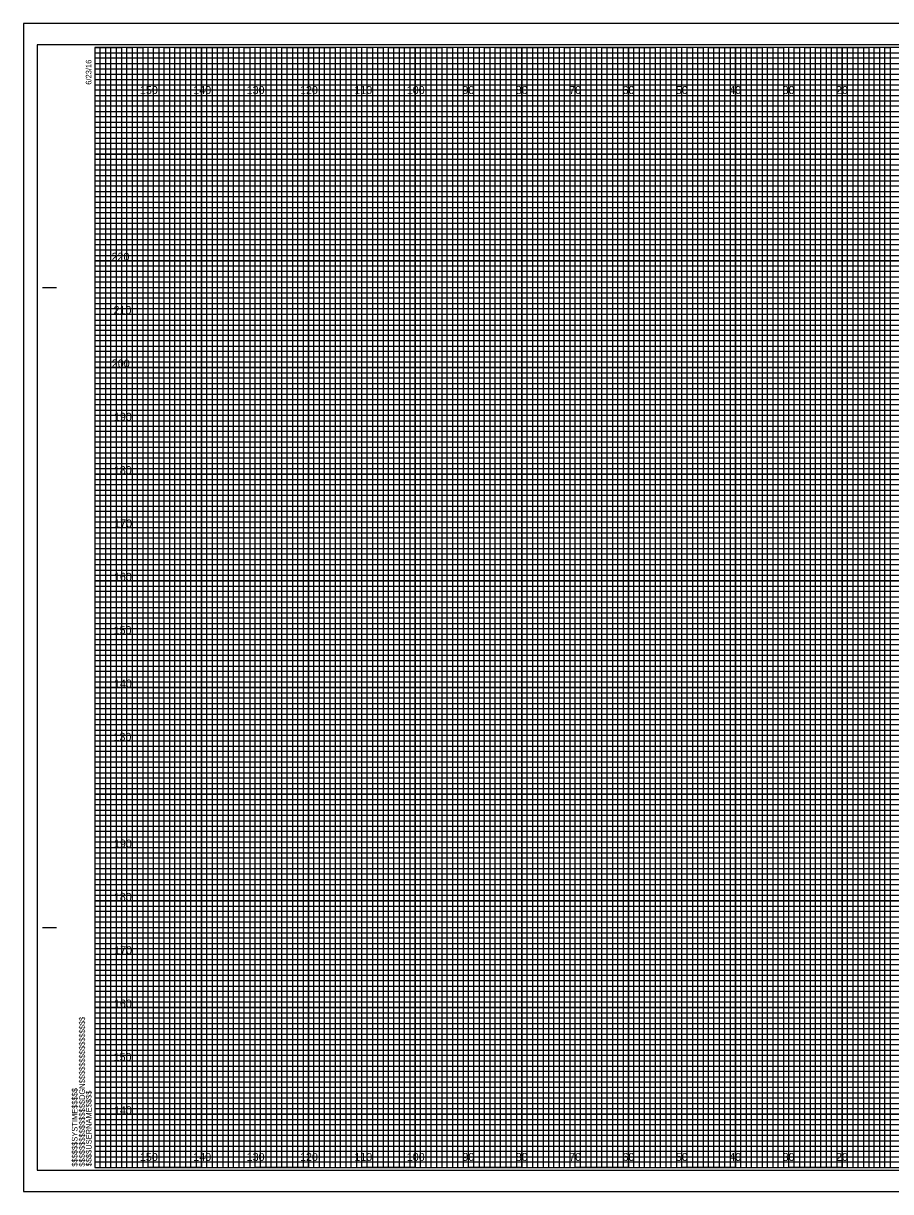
# Model space of a CAD drawing. Extents: x -13 to 323, y -5 to 1754.
# Drawn here: x -13.4 to 149.1, y 655.5 to 874.5 of the extents above; entities that cross this region are included whole.
import ezdxf

# ---------------------------------------------------------------- set-up
doc = ezdxf.new("R2010")
doc.units = 0
for name, color, linetype in [('Exist Cross Section Cell', 7, 'Continuous'), ('Exist XS Center Line Elevation Label', 7, 'Continuous'), ('Exist XS Ground Line', 7, 'Continuous'), ('Prop CMT Pvmt Course 1', 7, 'Continuous'), ('Prop CMT Pvmt Course 2', 7, 'Continuous'), ('Prop CMT Pvmt Course 3', 7, 'Continuous'), ('Prop CMT Shld Paved Course 1', 7, 'Continuous'), ('Prop CMT Shld Paved Course 2', 7, 'Continuous'), ('Prop CMT Subgrade Earthwork', 7, 'Continuous'), ('Prop XS Ditch Standard Text', 7, 'Continuous'), ('Scratch_Level_0', 7, 'Continuous')]:
    doc.layers.add(name, color=color, linetype=linetype)

msp = doc.modelspace()

# ---------------------------------------------------------------- linework, layer by layer
at = {"layer": 'Exist XS Center Line Elevation Label'}
for points in [[(0, 870), (5, 870), (5, 660), (15, 660), (15, 870), (25, 870), (25, 660), (35, 660), (35, 870), (45, 870), (45, 660), (55, 660), (55, 870), (65, 870), (65, 660), (75, 660), (75, 870), (85, 870), (85, 660), (95, 660), (95, 870), (105, 870), (105, 660), (115, 660), (115, 870), (125, 870), (125, 660), (135, 660), (135, 870), (145, 870), (145, 660), (155, 660)], [(0, 865), (275, 865)], [(0, 845), (320, 845), (320, 855), (0, 855)], [(0, 825), (320, 825), (320, 835), (0, 835)], [(0, 805), (320, 805), (320, 815), (0, 815)], [(0, 785), (320, 785), (320, 795), (0, 795)], [(0, 765), (320, 765), (320, 775), (0, 775)], [(0, 745), (320, 745), (320, 755), (0, 755)], [(0, 725), (320, 725), (320, 735), (0, 735)], [(0, 705), (320, 705), (320, 715), (0, 715)], [(0, 685), (320, 685), (320, 695), (0, 695)], [(0, 665), (320, 665), (320, 675), (0, 675)]]:
    msp.add_lwpolyline(points, dxfattribs=at)
at = {"layer": 'Exist XS Ground Line'}
for p, q in [((10, 870), (0, 870)), ((10, 660), (10, 870)), ((30, 870), (20, 870)), ((20, 870), (20, 660)), ((30, 660), (30, 870)), ((50, 870), (40, 870)), ((40, 870), (40, 660)), ((50, 660), (50, 870)), ((70, 870), (60, 870)), ((60, 870), (60, 660)), ((70, 660), (70, 870)), ((90, 870), (80, 870)), ((80, 870), (80, 660)), ((90, 660), (90, 870)), ((110, 870), (100, 870)), ((100, 870), (100, 660)), ((110, 660), (110, 870)), ((130, 870), (120, 870)), ((120, 870), (120, 660)), ((130, 660), (130, 870)), ((150, 870), (140, 870)), ((140, 870), (140, 660)), ((20, 660), (10, 660)), ((40, 660), (30, 660)), ((60, 660), (50, 660)), ((80, 660), (70, 660)), ((100, 660), (90, 660)), ((120, 660), (110, 660)), ((140, 660), (130, 660))]:
    msp.add_line(p, q, dxfattribs=at)
for points in [[(0, 860), (320, 860), (320, 850), (0, 850)], [(0, 840), (320, 840), (320, 830), (0, 830)], [(0, 820), (320, 820), (320, 810), (0, 810)], [(0, 800), (320, 800), (320, 790), (0, 790)], [(0, 780), (320, 780), (320, 770), (0, 770)], [(0, 760), (320, 760), (320, 750), (0, 750)], [(0, 740), (320, 740), (320, 730), (0, 730)], [(0, 720), (320, 720), (320, 710), (0, 710)], [(0, 700), (320, 700), (320, 690), (0, 690)], [(0, 680), (320, 680), (320, 670), (0, 670)]]:
    msp.add_lwpolyline(points, dxfattribs=at)
at = {"layer": 'Prop CMT Pvmt Course 1'}
for p, q in [((323.3, 874.5), (-13.4, 874.5)), ((-13.4, 874.5), (-13.4, 655.5)), ((-13.4, 655.5), (323.3, 655.5))]:
    msp.add_line(p, q, dxfattribs=at)
at = {"layer": 'Prop CMT Pvmt Course 2'}
msp.add_lwpolyline([(-13.4, 655.5), (323.3, 655.5), (323.3, 874.5), (-13.4, 874.5)], close=True, dxfattribs=at)
at = {"layer": 'Prop CMT Pvmt Course 3'}
msp.add_lwpolyline([(-10.8, 659.5), (322.4, 659.5), (322.4, 870.5), (-10.8, 870.5)], close=True, dxfattribs=at)
at = {"layer": 'Prop CMT Shld Paved Course 1'}
for p, q in [((-9.8, 825), (-7.3, 825)), ((-9.7, 825), (-7.2, 825)), ((-9.8, 705), (-7.3, 705)), ((-9.7, 705), (-7.2, 705)), ((0, 660), (0, 660)), ((0, 660), (0, 660)), ((0, 660), (0, 660)), ((0, 660), (0, 660)), ((0, 660), (0, 660)), ((0, 660), (0, 660)), ((0, 660), (0, 660))]:
    msp.add_line(p, q, dxfattribs=at)
msp.add_lwpolyline([(320, 870), (0, 870), (0, 660), (320, 660)], close=True, dxfattribs=at)
at = {"layer": 'Prop CMT Shld Paved Course 2'}
for points in [[(0, 660), (1, 660), (1, 870), (2, 870), (2, 660)], [(2, 660), (3, 660), (3, 870), (4, 870), (4, 660)], [(5, 660), (6, 660), (6, 870), (7, 870), (7, 660)], [(7, 660), (8, 660), (8, 870), (9, 870), (9, 660)], [(10, 660), (11, 660), (11, 870), (12, 870), (12, 660)], [(12, 660), (13, 660), (13, 870), (14, 870), (14, 660)], [(15, 660), (16, 660), (16, 870), (17, 870), (17, 660)], [(17, 660), (18, 660), (18, 870), (19, 870), (19, 660)], [(20, 660), (21, 660), (21, 870), (22, 870), (22, 660)], [(22, 660), (23, 660), (23, 870), (24, 870), (24, 660)], [(25, 660), (26, 660), (26, 870), (27, 870), (27, 660)], [(27, 660), (28, 660), (28, 870), (29, 870), (29, 660)], [(30, 660), (31, 660), (31, 870), (32, 870), (32, 660)], [(32, 660), (33, 660), (33, 870), (34, 870), (34, 660)], [(35, 660), (36, 660), (36, 870), (37, 870), (37, 660)], [(37, 660), (38, 660), (38, 870), (39, 870), (39, 660)], [(40, 660), (41, 660), (41, 870), (42, 870), (42, 660)], [(42, 660), (43, 660), (43, 870), (44, 870), (44, 660)], [(45, 660), (46, 660), (46, 870), (47, 870), (47, 660)], [(47, 660), (48, 660), (48, 870), (49, 870), (49, 660)], [(50, 660), (51, 660), (51, 870), (52, 870), (52, 660)], [(52, 660), (53, 660), (53, 870), (54, 870), (54, 660)], [(55, 660), (56, 660), (56, 870), (57, 870), (57, 660)], [(57, 660), (58, 660), (58, 870), (59, 870), (59, 660)], [(60, 660), (61, 660), (61, 870), (62, 870), (62, 660)], [(62, 660), (63, 660), (63, 870), (64, 870), (64, 660)], [(65, 660), (66, 660), (66, 870), (67, 870), (67, 660)], [(67, 660), (68, 660), (68, 870), (69, 870), (69, 660)], [(70, 660), (71, 660), (71, 870), (72, 870), (72, 660)], [(72, 660), (73, 660), (73, 870), (74, 870), (74, 660)], [(75, 660), (76, 660), (76, 870), (77, 870), (77, 660)], [(77, 660), (78, 660), (78, 870), (79, 870), (79, 660)], [(80, 660), (81, 660), (81, 870), (82, 870), (82, 660)], [(82, 660), (83, 660), (83, 870), (84, 870), (84, 660)], [(85, 660), (86, 660), (86, 870), (87, 870), (87, 660)], [(87, 660), (88, 660), (88, 870), (89, 870), (89, 660)], [(90, 660), (91, 660), (91, 870), (92, 870), (92, 660)], [(92, 660), (93, 660), (93, 870), (94, 870), (94, 660)], [(95, 660), (96, 660), (96, 870), (97, 870), (97, 660)], [(97, 660), (98, 660), (98, 870), (99, 870), (99, 660)], [(100, 660), (101, 660), (101, 870), (102, 870), (102, 660)], [(102, 660), (103, 660), (103, 870), (104, 870), (104, 660)], [(105, 660), (106, 660), (106, 870), (107, 870), (107, 660)], [(107, 660), (108, 660), (108, 870), (109, 870), (109, 660)], [(110, 660), (111, 660), (111, 870), (112, 870), (112, 660)], [(112, 660), (113, 660), (113, 870), (114, 870), (114, 660)], [(115, 660), (116, 660), (116, 870), (117, 870), (117, 660)], [(117, 660), (118, 660), (118, 870), (119, 870), (119, 660)], [(120, 660), (121, 660), (121, 870), (122, 870), (122, 660)], [(122, 660), (123, 660), (123, 870), (124, 870), (124, 660)], [(125, 660), (126, 660), (126, 870), (127, 870), (127, 660)], [(127, 660), (128, 660), (128, 870), (129, 870), (129, 660)], [(130, 660), (131, 660), (131, 870), (132, 870), (132, 660)], [(132, 660), (133, 660), (133, 870), (134, 870), (134, 660)], [(135, 660), (136, 660), (136, 870), (137, 870), (137, 660)], [(137, 660), (138, 660), (138, 870), (139, 870), (139, 660)], [(140, 660), (141, 660), (141, 870), (142, 870), (142, 660)], [(142, 660), (143, 660), (143, 870), (144, 870), (144, 660)], [(145, 660), (146, 660), (146, 870), (147, 870), (147, 660)], [(147, 660), (148, 660), (148, 870), (149, 870), (149, 660)]]:
    msp.add_lwpolyline(points, dxfattribs=at)
at = {"layer": 'Prop CMT Subgrade Earthwork'}
for p, q in [((10, 660), (10, 870)), ((20, 660), (20, 870)), ((30, 660), (30, 870)), ((40, 660), (40, 870)), ((50, 660), (50, 870)), ((60, 660), (60, 870)), ((70, 660), (70, 870)), ((80, 660), (80, 870)), ((90, 660), (90, 870)), ((100, 660), (100, 870)), ((110, 660), (110, 870)), ((120, 660), (120, 870)), ((130, 660), (130, 870)), ((140, 660), (140, 870)), ((0, 860), (320, 860)), ((0, 850), (320, 850)), ((0, 840), (320, 840)), ((0, 830), (320, 830)), ((0, 820), (320, 820)), ((0, 810), (320, 810)), ((0, 800), (320, 800)), ((0, 790), (320, 790)), ((0, 780), (320, 780)), ((0, 770), (320, 770)), ((0, 760), (320, 760)), ((0, 750), (320, 750)), ((0, 740), (320, 740)), ((0, 730), (320, 730)), ((0, 720), (320, 720)), ((0, 710), (320, 710)), ((0, 700), (320, 700)), ((0, 690), (320, 690)), ((0, 680), (320, 680)), ((0, 670), (320, 670))]:
    msp.add_line(p, q, dxfattribs=at)
at = {"layer": 'Scratch_Level_0'}
for p, q in [((0, 869), (260, 869)), ((260, 867.98), (0, 867.98)), ((0, 867.98), (0, 867)), ((0, 867), (260, 867)), ((260, 865.89), (0, 865.89)), ((0, 865.89), (0, 864)), ((0, 864), (320, 864))]:
    msp.add_line(p, q, dxfattribs=at)
for points in [[(0, 863), (270, 863), (320, 863), (320, 862), (0, 862)], [(0, 861), (320, 861), (320, 859), (0, 859)], [(0, 858), (320, 858), (320, 857), (0, 856.98)], [(0, 856), (320, 856), (320, 854), (0, 854)], [(0, 853), (320, 853), (320, 852), (0, 852)], [(0, 851), (320, 851), (320, 849), (0, 849)], [(0, 848), (320, 848), (320, 847), (0, 847)], [(0, 846), (320, 846), (320, 844), (0, 844)], [(0, 843), (320, 843), (320, 842), (0, 842)], [(0, 841), (320, 841), (320, 839), (0, 839)], [(0, 838), (320, 838), (320, 837), (0, 837)], [(0, 836), (320, 836), (320, 833.95), (320, 833), (320, 832), (0, 832)], [(0, 834), (320, 834), (320, 833), (0, 833)], [(0, 831), (320, 831), (320, 829), (0, 829.03)], [(0, 829.03), (320, 829), (320, 828), (0, 828)], [(0, 827), (320, 827), (320, 826), (0, 826)], [(0, 824), (320, 824), (320, 823), (0, 823)], [(0, 822), (320, 822), (320, 821), (0, 821)], [(-0.07, 818.89), (320, 818.89), (320, 817.88), (-0.07, 817.88)], [(0, 817), (320, 817), (320, 816), (0, 816)], [(0, 814), (320, 814), (320, 813), (0, 813)], [(0, 812), (320, 812), (320, 811), (0, 811)], [(0, 809), (320, 809), (320, 808), (0, 808)], [(0, 807), (320, 807), (320, 806), (0, 806)], [(0, 804), (320, 804), (320, 803), (0, 803)], [(0, 802), (320, 802), (320, 801), (0, 801)], [(0, 799), (320, 799), (319.99, 797.98), (0, 798)], [(0, 797), (320, 797), (320, 796), (0, 796)], [(0, 794), (320, 794), (320, 793), (0, 793)], [(0, 792), (320, 792), (320, 791), (0, 791)], [(0, 789), (320, 789), (320, 788), (0, 788)], [(0, 787), (320, 787), (320, 786), (0, 786)], [(0, 784), (320, 784), (320, 783), (0, 783)], [(0, 782), (320, 782), (320, 781), (0, 781)], [(0, 779), (320, 779), (320, 778), (0, 778)], [(0, 776.99), (320.07, 776.91), (320, 776), (0, 776)], [(0, 774), (320, 774), (320, 773), (0, 773)], [(0, 772), (320, 772), (320, 771), (0, 771)], [(0, 769), (320, 769), (320, 768), (0, 768)], [(0, 767), (320, 767), (320, 766), (0, 766)], [(0, 764), (320, 764), (320, 763), (0, 763)], [(0, 762), (320, 762), (320, 761), (0, 761)], [(0, 759), (320, 759), (320, 758), (0, 758)], [(0, 757), (320, 757), (320, 756), (0, 756)], [(0, 754), (320, 754), (320, 753), (0, 753)], [(0, 752), (320, 752), (320, 751), (0, 751)], [(0, 749), (320, 749), (320, 748), (0, 748)], [(0, 747), (320, 747), (320, 746), (0, 746)], [(0, 744), (320, 744), (320, 743), (0, 743)], [(0, 742), (320, 742), (320, 741), (0, 741)], [(0, 739), (320, 739), (319.99, 737.98), (0, 738)], [(0, 737), (320, 737), (320, 736), (0, 736)], [(0, 734), (320, 734), (320, 733), (0, 733)], [(0, 732), (320, 732), (320, 731), (0, 731)], [(0, 729), (320, 729), (320, 728), (0, 728)], [(0, 727), (320, 727), (320, 726), (0, 726)], [(0, 724), (320, 724), (320, 723), (0, 723)], [(0, 722), (320, 722), (320, 721), (0, 721)], [(0, 719), (320, 719), (320, 718), (0, 718)], [(0, 716.99), (320.07, 716.91), (320, 716), (0, 716)], [(0, 714), (320, 714), (320, 713), (0, 713)], [(0, 712), (320, 712), (320, 711), (0, 711)], [(0, 709), (320, 709), (320, 708), (0, 708)], [(0, 707), (320, 707), (320, 706), (0, 706)], [(0, 704), (320, 704), (320, 703), (0, 703)], [(0, 702), (320, 702), (320, 701), (0, 701)], [(0, 699), (320, 699), (320, 698), (0, 698)], [(0, 697), (320, 697), (320, 696), (0, 696)], [(0, 694), (320, 694), (320, 693), (0, 693)], [(0, 692), (320, 692), (320, 691), (0, 691)], [(0, 689), (320, 689), (320, 688), (0, 688)], [(0, 687), (320, 687), (320, 686), (0, 686)], [(0, 684), (320, 684), (320, 683), (0, 683)], [(0, 682), (320, 682), (320, 681), (0, 681)], [(0, 679), (320, 679), (320, 678), (0, 678)], [(0, 677), (320, 677), (320, 676), (0, 676)], [(0, 674), (320, 674), (320, 673), (0, 673)], [(0, 672), (320, 672), (320, 671), (0, 671)], [(0, 669), (320, 669), (320, 668), (0, 668)], [(0, 667), (320, 667), (320, 666), (0, 666)], [(0, 664), (320, 664), (320, 663), (0, 663)], [(0, 662), (320, 662), (320, 661), (0, 661)]]:
    msp.add_lwpolyline(points, dxfattribs=at)

# ---------------------------------------------------------------- texts
at = {"layer": 'Exist Cross Section Cell'}
for s, p in [('220', (3.12, 830)), ('210', (3.5, 820)), ('200', (3.17, 810)), ('190', (3.57, 800)), ('180', (3.55, 790)), ('170', (3.61, 780)), ('160', (3.57, 770)), ('150', (3.52, 760)), ('140', (3.57, 750)), ('130', (3.49, 740)), ('190', (3.57, 720)), ('180', (3.55, 710)), ('170', (3.61, 700)), ('160', (3.57, 690)), ('150', (3.52, 680)), ('140', (3.57, 670))]:
    msp.add_text(s, height=1.5, dxfattribs=at).set_placement(p)
at = {"layer": 'Prop CMT Shld Paved Course 1'}
for s, p in [('6/23/16', (-0.65, 863)), ('$$$$$$$$$$$$$$$$DGN$$$$$$$$$$$$$$$$', (-1.88, 660.18)), ('$$$$$$SYSTIME$$$$$', (-3.26, 660.18)), ('$$$$USERNAME$$$$', (-0.62, 660.23))]:
    msp.add_text(s, height=1.05, rotation=90, dxfattribs=at).set_placement(p)
at = {"layer": 'Prop XS Ditch Standard Text'}
for s, p in [('150', (8.44, 861.25)), ('140', (18.44, 861.25)), ('130', (28.44, 861.25)), ('120', (38.44, 861.25)), ('110', (48.62, 861.25)), ('100', (58.44, 861.25)), ('90', (68.86, 861.25)), ('80', (78.86, 861.25)), ('70', (88.86, 861.25)), ('60', (98.86, 861.25)), ('50', (108.86, 861.25)), ('40', (118.86, 861.25)), ('30', (128.86, 861.25)), ('20', (138.86, 861.25)), ('150', (8.44, 661.25)), ('140', (18.44, 661.25)), ('130', (28.44, 661.25)), ('120', (38.44, 661.25)), ('110', (48.62, 661.25)), ('100', (58.44, 661.25)), ('90', (68.86, 661.25)), ('80', (78.86, 661.25)), ('70', (88.86, 661.25)), ('60', (98.86, 661.25)), ('50', (108.86, 661.25)), ('40', (118.86, 661.25)), ('30', (128.86, 661.25)), ('20', (138.86, 661.25))]:
    msp.add_text(s, height=1.5, dxfattribs=at).set_placement(p)

doc.saveas('drawing.dxf')
